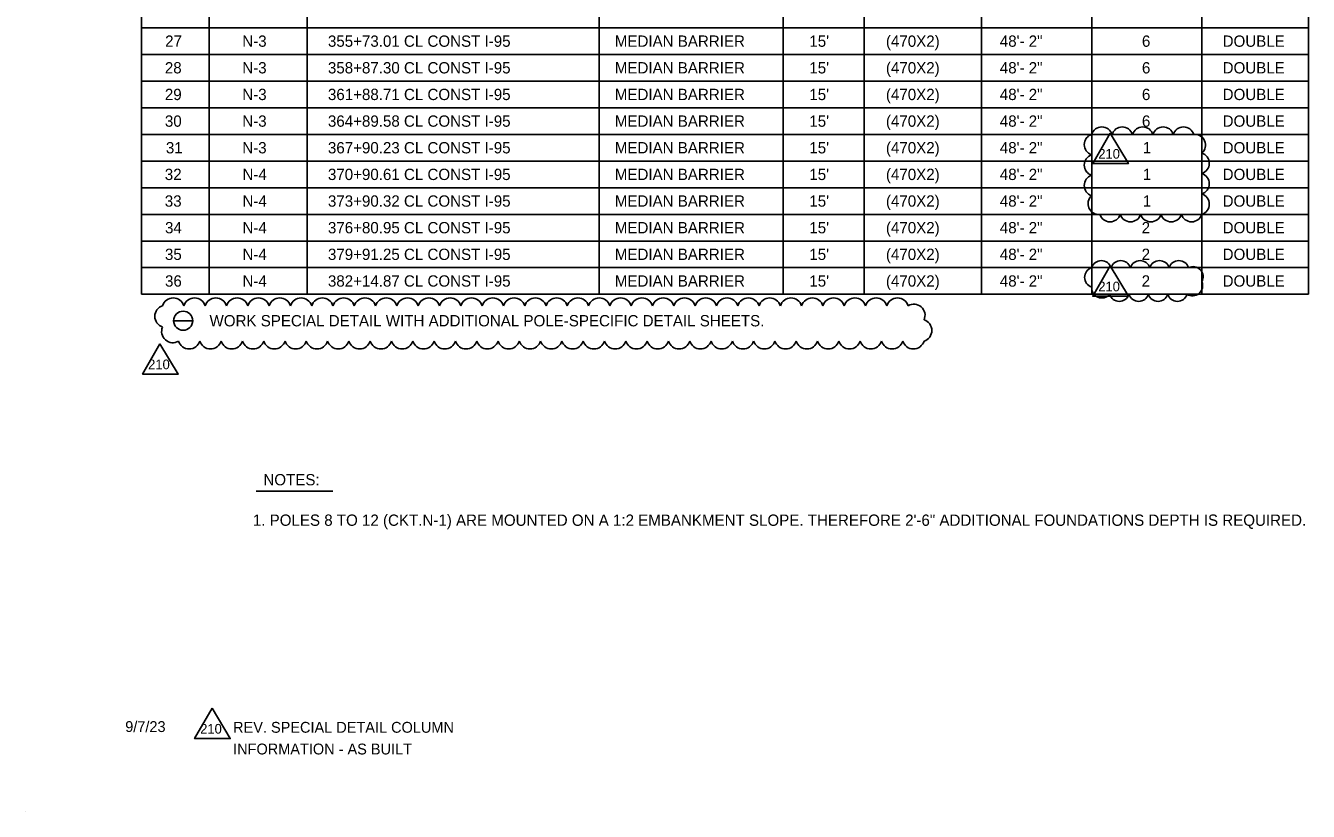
# Model space of a CAD drawing. Extents: x -816.7 to -727.6, y -2197.9 to -2187.8.
# Drawn here: x -816.67 to -808.72, y -2197.9 to -2193.03 of the extents above; entities that cross this region are included whole.
import ezdxf

# ---------------------------------------------------------------- set-up
doc = ezdxf.new("R2010")
doc.units = 0
for name, color, linetype in [('ClipBorder_dp', 7, 'Continuous'), ('MatchLines_dp', 7, 'Continuous'), ('NorthArw_dp', 7, 'Continuous'), ('PlotBorder_dp', 7, 'Continuous'), ('Scale_dp', 7, 'Continuous'), ('SignPanel_ep', 7, 'Continuous'), ('TextMisc', 7, 'Continuous')]:
    doc.layers.add(name, color=color, linetype=linetype)

msp = doc.modelspace()

# ---------------------------------------------------------------- linework, layer by layer
at = {"layer": 'ClipBorder_dp'}
for p, q in [((-815.7519, -2194.8609), (-815.6333, -2194.8609)), ((-815.7519, -2194.8609), (-815.6333, -2194.8609)), ((-815.2397, -2195.9158), (-814.7646, -2195.9158))]:
    msp.add_line(p, q, dxfattribs=at)
msp.add_circle((-815.6926, -2194.8609), 0.0593, dxfattribs=at)
msp.add_arc((-815.6926, -2194.8609), 0.0593, 0, 180, dxfattribs=at)
at = {"layer": 'MatchLines_dp'}
for p, q in [((-815.9511, -2193.0473), (-808.7211, -2193.0473)), ((-815.9511, -2193.0473), (-808.7211, -2193.0473)), ((-815.9511, -2193.2123), (-808.7211, -2193.2123)), ((-815.9511, -2193.2123), (-808.7211, -2193.2123)), ((-815.9511, -2193.3773), (-808.7211, -2193.3773)), ((-815.9511, -2193.3773), (-808.7211, -2193.3773)), ((-815.9511, -2193.5423), (-808.7211, -2193.5423)), ((-815.9511, -2193.5423), (-808.7211, -2193.5423)), ((-815.9511, -2193.7073), (-808.7211, -2193.7073)), ((-815.9511, -2193.7073), (-808.7211, -2193.7073)), ((-815.9511, -2193.8723), (-808.7211, -2193.8723)), ((-815.9511, -2193.8723), (-808.7211, -2193.8723)), ((-815.9511, -2194.0373), (-808.7211, -2194.0373)), ((-815.9511, -2194.0373), (-808.7211, -2194.0373)), ((-815.9511, -2194.2023), (-808.7211, -2194.2023)), ((-815.9511, -2194.2023), (-808.7211, -2194.2023)), ((-815.9511, -2194.3673), (-808.7211, -2194.3673)), ((-815.9511, -2194.3673), (-808.7211, -2194.3673)), ((-815.9511, -2194.5323), (-808.7211, -2194.5323)), ((-815.9511, -2194.5323), (-808.7211, -2194.5323))]:
    msp.add_line(p, q, dxfattribs=at)
at = {"layer": 'NorthArw_dp'}
for p, q in [((-815.9511, -2188.0973), (-815.9511, -2194.6973)), ((-808.7211, -2188.0973), (-808.7211, -2194.6973)), ((-808.7211, -2188.0973), (-808.7211, -2194.6973)), ((-815.9511, -2194.6973), (-808.7211, -2194.6973)), ((-810.7461, -2194.6973), (-809.3811, -2194.6973))]:
    msp.add_line(p, q, dxfattribs=at)
at = {"layer": 'PlotBorder_dp'}
for points in [[(-809.9493, -2193.6994), (-810.057, -2193.8875), (-809.8364, -2193.8875)], [(-809.9493, -2194.5208), (-810.057, -2194.7089), (-809.8364, -2194.7089)], [(-815.8363, -2195.0034), (-815.944, -2195.1915), (-815.7234, -2195.1915)], [(-815.5137, -2197.2596), (-815.6215, -2197.4477), (-815.4008, -2197.4477)]]:
    msp.add_lwpolyline(points, close=True, dxfattribs=at)
for centre, radius, start, end in [((-810.0004, -2193.7272), 0.0663, 17.5, 162.5), ((-809.874, -2193.7272), 0.0663, 17.5, 162.5), ((-809.7475, -2193.7272), 0.0663, 17.5, 162.5), ((-809.6211, -2193.7272), 0.0663, 17.5, 162.5), ((-809.4947, -2193.7272), 0.0663, 17.5, 162.5), ((-810.0436, -2193.7705), 0.0663, 107.5, 252.5), ((-809.4245, -2193.7731), 0.0662, 311.04336, 96.04336), ((-809.401, -2193.8862), 0.0663, 287.5, 72.5), ((-810.0436, -2193.8969), 0.0663, 107.5, 252.5), ((-810.0436, -2194.0233), 0.0663, 107.5, 252.5), ((-809.401, -2194.0126), 0.0663, 287.5, 72.5), ((-810.0201, -2194.1364), 0.0662, 131.04336, 276.04336), ((-809.401, -2194.1391), 0.0663, 287.5, 72.5), ((-809.9499, -2194.1823), 0.0663, 197.5, 342.5), ((-809.8235, -2194.1823), 0.0663, 197.5, 342.5), ((-809.6971, -2194.1823), 0.0663, 197.5, 342.5), ((-809.5707, -2194.1823), 0.0663, 197.5, 342.5), ((-809.4443, -2194.1823), 0.0663, 197.5, 342.5), ((-810.0447, -2194.5923), 0.0629, 107.5, 252.5), ((-810.0036, -2194.5512), 0.0629, 17.5, 162.5), ((-809.8835, -2194.5512), 0.0629, 17.5, 162.5), ((-809.7635, -2194.5512), 0.0629, 17.5, 162.5), ((-809.6435, -2194.5512), 0.0629, 17.5, 162.5), ((-809.5234, -2194.5512), 0.0629, 17.5, 162.5), ((-809.436, -2194.5888), 0.0629, 330.87934, 115.87934), ((-809.4389, -2194.644), 0.0629, 237.99061, 22.99061), ((-810.0009, -2194.6572), 0.0629, 175.48211, 320.48211), ((-809.8924, -2194.6783), 0.0629, 197.5, 342.5), ((-809.7723, -2194.6783), 0.0629, 197.5, 342.5), ((-809.6523, -2194.6783), 0.0629, 197.5, 342.5), ((-809.5323, -2194.6783), 0.0629, 197.5, 342.5), ((-815.7993, -2194.8337), 0.0692, 107.5, 252.5), ((-815.7541, -2194.7886), 0.0692, 17.5, 162.5), ((-815.6221, -2194.7886), 0.0692, 17.5, 162.5), ((-815.4902, -2194.7886), 0.0692, 17.5, 162.5), ((-815.3582, -2194.7886), 0.0692, 17.5, 162.5), ((-815.2262, -2194.7886), 0.0692, 17.5, 162.5), ((-815.0942, -2194.7886), 0.0692, 17.5, 162.5), ((-814.9622, -2194.7886), 0.0692, 17.5, 162.5), ((-814.8303, -2194.7886), 0.0692, 17.5, 162.5), ((-814.6983, -2194.7886), 0.0692, 17.5, 162.5), ((-814.5663, -2194.7886), 0.0692, 17.5, 162.5), ((-814.4343, -2194.7886), 0.0692, 17.5, 162.5), ((-814.3023, -2194.7886), 0.0692, 17.5, 162.5), ((-814.1703, -2194.7886), 0.0692, 17.5, 162.5), ((-814.0384, -2194.7886), 0.0692, 17.5, 162.5), ((-813.9064, -2194.7886), 0.0692, 17.5, 162.5), ((-813.7744, -2194.7886), 0.0692, 17.5, 162.5), ((-813.6424, -2194.7886), 0.0692, 17.5, 162.5), ((-813.5104, -2194.7886), 0.0692, 17.5, 162.5), ((-813.3784, -2194.7886), 0.0692, 17.5, 162.5), ((-813.2465, -2194.7886), 0.0692, 17.5, 162.5), ((-813.1145, -2194.7886), 0.0692, 17.5, 162.5), ((-812.9825, -2194.7886), 0.0692, 17.5, 162.5), ((-812.8505, -2194.7886), 0.0692, 17.5, 162.5), ((-812.7185, -2194.7886), 0.0692, 17.5, 162.5), ((-812.5865, -2194.7886), 0.0692, 17.5, 162.5), ((-812.4546, -2194.7886), 0.0692, 17.5, 162.5), ((-812.3226, -2194.7886), 0.0692, 17.5, 162.5), ((-812.1906, -2194.7886), 0.0692, 17.5, 162.5), ((-812.0586, -2194.7886), 0.0692, 17.5, 162.5), ((-811.9266, -2194.7886), 0.0692, 17.5, 162.5), ((-811.7946, -2194.7886), 0.0692, 17.5, 162.5), ((-811.6627, -2194.7886), 0.0692, 17.5, 162.5), ((-811.5307, -2194.7886), 0.0692, 17.5, 162.5), ((-811.3987, -2194.7886), 0.0692, 17.5, 162.5), ((-811.2667, -2194.7886), 0.0692, 17.5, 162.5), ((-811.1652, -2194.8271), 0.0691, 335.91104, 120.91104), ((-811.1229, -2194.9213), 0.0692, 287.5, 72.5), ((-815.757, -2194.928), 0.0691, 155.91104, 300.91104), ((-815.6555, -2194.9665), 0.0692, 197.5, 342.5), ((-815.5235, -2194.9665), 0.0692, 197.5, 342.5), ((-815.3915, -2194.9665), 0.0692, 197.5, 342.5), ((-815.2595, -2194.9665), 0.0692, 197.5, 342.5), ((-815.1276, -2194.9665), 0.0692, 197.5, 342.5), ((-814.9956, -2194.9665), 0.0692, 197.5, 342.5), ((-814.8636, -2194.9665), 0.0692, 197.5, 342.5), ((-814.7316, -2194.9665), 0.0692, 197.5, 342.5), ((-814.5996, -2194.9665), 0.0692, 197.5, 342.5), ((-814.4676, -2194.9665), 0.0692, 197.5, 342.5), ((-814.3357, -2194.9665), 0.0692, 197.5, 342.5), ((-814.2037, -2194.9665), 0.0692, 197.5, 342.5), ((-814.0717, -2194.9665), 0.0692, 197.5, 342.5), ((-813.9397, -2194.9665), 0.0692, 197.5, 342.5), ((-813.8077, -2194.9665), 0.0692, 197.5, 342.5), ((-813.6757, -2194.9665), 0.0692, 197.5, 342.5), ((-813.5438, -2194.9665), 0.0692, 197.5, 342.5), ((-813.4118, -2194.9665), 0.0692, 197.5, 342.5), ((-813.2798, -2194.9665), 0.0692, 197.5, 342.5), ((-813.1478, -2194.9665), 0.0692, 197.5, 342.5), ((-813.0158, -2194.9665), 0.0692, 197.5, 342.5), ((-812.8838, -2194.9665), 0.0692, 197.5, 342.5), ((-812.7519, -2194.9665), 0.0692, 197.5, 342.5), ((-812.6199, -2194.9665), 0.0692, 197.5, 342.5), ((-812.4879, -2194.9665), 0.0692, 197.5, 342.5), ((-812.3559, -2194.9665), 0.0692, 197.5, 342.5), ((-812.2239, -2194.9665), 0.0692, 197.5, 342.5), ((-812.0919, -2194.9665), 0.0692, 197.5, 342.5), ((-811.96, -2194.9665), 0.0692, 197.5, 342.5), ((-811.828, -2194.9665), 0.0692, 197.5, 342.5), ((-811.696, -2194.9665), 0.0692, 197.5, 342.5), ((-811.564, -2194.9665), 0.0692, 197.5, 342.5), ((-811.432, -2194.9665), 0.0692, 197.5, 342.5), ((-811.3001, -2194.9665), 0.0692, 197.5, 342.5), ((-811.1681, -2194.9665), 0.0692, 197.5, 342.5)]:
    msp.add_arc(centre, radius, start, end, dxfattribs=at)
at = {"layer": 'Scale_dp'}
for p, q in [((-815.5311, -2188.4273), (-815.5311, -2194.6973)), ((-815.5311, -2188.4273), (-815.5311, -2194.6973)), ((-814.9236, -2188.4273), (-814.9236, -2194.6973)), ((-814.9236, -2188.4273), (-814.9236, -2194.6973)), ((-813.1161, -2188.4273), (-813.1161, -2194.6973)), ((-813.1161, -2188.4273), (-813.1161, -2194.6973)), ((-811.9761, -2188.4273), (-811.9761, -2194.6973)), ((-811.9761, -2188.4273), (-811.9761, -2194.6973)), ((-811.4736, -2188.4273), (-811.4736, -2194.6973)), ((-811.4736, -2188.4273), (-811.4736, -2194.6973)), ((-810.7461, -2188.4273), (-810.7461, -2194.6973)), ((-810.7461, -2188.4273), (-810.7461, -2194.6973)), ((-810.0636, -2188.4273), (-810.0636, -2194.6973)), ((-810.0636, -2188.4273), (-810.0636, -2194.6973)), ((-809.3811, -2188.4273), (-809.3811, -2194.6973)), ((-809.3811, -2194.5323), (-809.3811, -2194.6973))]:
    msp.add_line(p, q, dxfattribs=at)
at = {"layer": 'TextMisc'}
msp.add_line((-816.6686, -2197.8985), (-816.6686, -2197.8985), dxfattribs=at)

# ---------------------------------------------------------------- texts
at = {"layer": 'ClipBorder_dp'}
for s, p in [('27', (-815.8044, -2193.1648)), ('N-3', (-815.3265, -2193.1648)), ('355+73.01 CL CONST I-95', (-814.7957, -2193.1648)), ('MEDIAN BARRIER', (-813.0182, -2193.1648)), ("15'", (-811.8128, -2193.1648)), ('(470X2)', (-811.3383, -2193.1648)), ('48\'- 2"', (-810.6327, -2193.1648)), ('6', (-809.7523, -2193.1648)), ('DOUBLE', (-809.2521, -2193.1648)), ('28', (-815.8061, -2193.3298)), ('N-3', (-815.3265, -2193.3298)), ('358+87.30 CL CONST I-95', (-814.7957, -2193.3298)), ('MEDIAN BARRIER', (-813.0182, -2193.3298)), ("15'", (-811.8128, -2193.3298)), ('(470X2)', (-811.3383, -2193.3298)), ('48\'- 2"', (-810.6327, -2193.3298)), ('6', (-809.7523, -2193.3298)), ('DOUBLE', (-809.2521, -2193.3298)), ('29', (-815.806, -2193.4948)), ('N-3', (-815.3265, -2193.4948)), ('361+88.71 CL CONST I-95', (-814.7957, -2193.4948)), ('MEDIAN BARRIER', (-813.0182, -2193.4948)), ("15'", (-811.8128, -2193.4948)), ('(470X2)', (-811.3383, -2193.4948)), ('48\'- 2"', (-810.6327, -2193.4948)), ('6', (-809.7523, -2193.4948)), ('DOUBLE', (-809.2521, -2193.4948)), ('30', (-815.8058, -2193.6598)), ('N-3', (-815.3265, -2193.6598)), ('364+89.58 CL CONST I-95', (-814.7957, -2193.6598)), ('MEDIAN BARRIER', (-813.0182, -2193.6598)), ("15'", (-811.8128, -2193.6598)), ('(470X2)', (-811.3383, -2193.6598)), ('48\'- 2"', (-810.6327, -2193.6598)), ('6', (-809.7523, -2193.6598)), ('DOUBLE', (-809.2521, -2193.6598)), ('(470X2)', (-811.3383, -2193.8248)), ('31', (-815.7996, -2193.8248)), ('N-3', (-815.3265, -2193.8248)), ('367+90.23 CL CONST I-95', (-814.7957, -2193.8248)), ('MEDIAN BARRIER', (-813.0182, -2193.8248)), ("15'", (-811.8128, -2193.8248)), ('48\'- 2"', (-810.6327, -2193.8248)), ('1', (-809.747, -2193.8248)), ('DOUBLE', (-809.2521, -2193.8248)), ('32', (-815.8064, -2193.9898)), ('N-4', (-815.3251, -2193.9898)), ('370+90.61 CL CONST I-95', (-814.7957, -2193.9898)), ('MEDIAN BARRIER', (-813.0182, -2193.9898)), ("15'", (-811.8128, -2193.9898)), ('(470X2)', (-811.3383, -2193.9898)), ('48\'- 2"', (-810.6327, -2193.9898)), ('1', (-809.747, -2193.9898)), ('DOUBLE', (-809.2521, -2193.9898)), ('33', (-815.8064, -2194.1548)), ('N-4', (-815.3251, -2194.1548)), ('373+90.32 CL CONST I-95', (-814.7957, -2194.1548)), ('MEDIAN BARRIER', (-813.0182, -2194.1548)), ("15'", (-811.8128, -2194.1548)), ('(470X2)', (-811.3383, -2194.1548)), ('48\'- 2"', (-810.6327, -2194.1548)), ('1', (-809.747, -2194.1548)), ('DOUBLE', (-809.2521, -2194.1548)), ('34', (-815.805, -2194.3198)), ('N-4', (-815.3251, -2194.3198)), ('376+80.95 CL CONST I-95', (-814.7957, -2194.3198)), ('MEDIAN BARRIER', (-813.0182, -2194.3198)), ("15'", (-811.8128, -2194.3198)), ('(470X2)', (-811.3383, -2194.3198)), ('48\'- 2"', (-810.6327, -2194.3198)), ('2', (-809.7537, -2194.3198)), ('DOUBLE', (-809.2521, -2194.3198)), ('35', (-815.8055, -2194.4848)), ('N-4', (-815.3251, -2194.4848)), ('379+91.25 CL CONST I-95', (-814.7957, -2194.4848)), ('MEDIAN BARRIER', (-813.0182, -2194.4848)), ("15'", (-811.8128, -2194.4848)), ('(470X2)', (-811.3383, -2194.4848)), ('48\'- 2"', (-810.6327, -2194.4848)), ('2', (-809.7537, -2194.4848)), ('DOUBLE', (-809.2521, -2194.4848)), ('36', (-815.805, -2194.6498)), ('N-4', (-815.3251, -2194.6498)), ('382+14.87 CL CONST I-95', (-814.7957, -2194.6498)), ('MEDIAN BARRIER', (-813.0182, -2194.6498)), ("15'", (-811.8128, -2194.6498)), ('(470X2)', (-811.3383, -2194.6498)), ('48\'- 2"', (-810.6327, -2194.6498)), ('2', (-809.7537, -2194.6498)), ('DOUBLE', (-809.2521, -2194.6498)), ('WORK SPECIAL DETAIL WITH ADDITIONAL POLE-SPECIFIC DETAIL SHEETS.', (-815.5294, -2194.8959)), ('NOTES:', (-815.1955, -2195.8801)), ('1. POLES 8 TO 12 (CKT.N-1) ARE MOUNTED ON A 1:2 EMBANKMENT SLOPE. THEREFORE 2\'-6" ADDITIONAL FOUNDATIONS DEPTH IS REQUIRED.', (-815.2609, -2196.1308))]:
    msp.add_text(s, height=0.07, dxfattribs=at).set_placement(p)
at = {"layer": 'PlotBorder_dp'}
for p in [(-810.0225, -2193.8573), (-810.0225, -2194.6788), (-815.9095, -2195.1613), (-815.587, -2197.4175)]:
    msp.add_text('210', height=0.05998, rotation=0, dxfattribs=at).set_placement(p)
at = {"layer": 'SignPanel_ep'}
for s, p in [('9/7/23', (-816.0516, -2197.4075)), ('REV. SPECIAL DETAIL COLUMN ', (-815.3832, -2197.412)), ('INFORMATION - AS BUILT', (-815.3832, -2197.5464))]:
    msp.add_text(s, height=0.0672, rotation=360, dxfattribs=at).set_placement(p)

doc.saveas('drawing.dxf')
